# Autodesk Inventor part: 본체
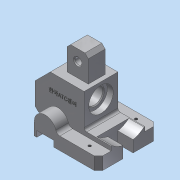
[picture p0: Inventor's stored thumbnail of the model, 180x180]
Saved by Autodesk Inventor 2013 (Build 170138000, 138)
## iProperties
Created: 2016-11
Part Number: 본체
Material: 알루미늄 6061
Document SubType Name: Modeling
Designer: Administrator
Density: 2.71 g/cm^3
Mass: 453.586 g
Surface Area: 313.387 cm^2
Volume: 167.375 cm^3
Author: Administrator
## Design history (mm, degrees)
sketch "스케치1"
  geometry: L1 (-38, 35)-(38, 35); L2 (38, 35)-(38, -35); L3 (38, -35)-(-38, -35); L4 (-38, -35)-(-38, 35); 3 further points
  constraints: 8 end point, 2 midpoint, 2 parallel, 1 horizontal, 1 horizontal alignment, 1 perpendicular, 1 vertical alignment
  dimensions: "d0" = 76 distance of L1.start L1.end; "d2" = 70 distance of L1.end L2.end
extrude "돌출1" new body sketch "스케치1" distance "d3" = 15; taper "d4" = 0 deg
sketch "스케치2"
  geometry: L1 (-35, 35)-(-35, -35); L2 (-15, 35)-(-15, -35); L3 (38, 35)-(-38, 35) reference; L4 (-38, -35)-(38, -35) reference; 1 further point
  constraints: 4 end point, 4 point on line, 1 parallel, 1 vertical
  dimensions: "d5" = 20 distance between parallel lines of L2 L1; "d6" = 3 distance from line of L1 L4.start
extrude "돌출2" cut sketch "스케치2" distance "d7" = 7; taper "d8" = 0 deg
sketch "스케치3"
  geometry: L1 (0, 0)-(76, 0) reference; A1 r 13 centre (13, 0) between (26, 0) and (0, 0); 1 further point
  constraints: 2 point on circle, 2 point on line, 1 centre point, 1 end point
  dimensions: "d9" = 26 diameter of A1
extrude "돌출3" join sketch "스케치3" distance "d11" = 70; taper "d12" = 0 deg
node "작업 평면1"
sketch "스케치4"
  geometry: L1 (-52, 20)-(6, 20); L2 (6, 20)-(6, -20); L3 (6, -20)-(-52, -20); L4 (-52, -20)-(-52, 20); L5 (38, -35)-(38, 35) reference; L6 (-38, 35)-(-38, -35) reference; 2 further points
  constraints: 8 end point, 2 parallel, 1 horizontal, 1 horizontal alignment, 1 midpoint, 1 perpendicular
  dimensions: "d117" = 40 distance between parallel lines of L3 L1; "d119" = 90 distance between parallel lines of L5 L4; "d120" = 58 distance from line of L1.start L2
extrude "돌출4" join sketch "스케치4" distance "d18" = 48; taper "d19" = 0 deg
chamfer "모따기1" distance "d20" = 18; stored, may be unused: second distance "d21" = 2, angle "d22" = 45 deg
chamfer "모따기2" distance "d23" = 4; stored, may be unused: second distance "d24" = 2, angle "d25" = 45 deg
chamfer "모따기3" distance "d26" = 5; stored, may be unused: second distance "d27" = 2, angle "d28" = 45 deg
chamfer "모따기4" distance "d29" = 5; stored, may be unused: second distance "d30" = 2, angle "d31" = 45 deg
fillet "모깎기1" dims "d32" = 5
node "작업 평면2"
sketch "스케치5"
  geometry: L1 (-24, 10)-(1, 10); L2 (1, 10)-(1, -10); L3 (1, -10)-(-24, -10); L4 (-24, -10)-(-24, 10); L5 (6, 20)-(6, -20) reference; 2 further points
  constraints: 8 end point, 2 parallel, 1 horizontal, 1 horizontal alignment, 1 midpoint, 1 perpendicular
  dimensions: "d34" = 5 distance between parallel lines of L2 L5; "d35" = 25 distance of L1.start L1.end; "d36" = 20 distance of L1.end L2.end
extrude "돌출5" join sketch "스케치5" distance "d37" = 40; taper "d38" = 0 deg
chamfer "모따기5" distance "d39" = 4; stored, may be unused: second distance "d40" = 2, angle "d41" = 45 deg
node "작업 평면3"
node "작업 평면5"
  node "작업 평면4"
sketch "스케치8"
  geometry: L1 (6, 20)-(6, -20) reference; L2 (6, 20)-(38, 20); L3 (38, 20)-(38, -20); L4 (38, -20)-(6, -20); L5 (6, -20)-(6, 20); L6 (-34, 20)-(6, 20) reference; L7 (6, -20)-(-34, -20) reference; 4 further points; 1 other entity
  constraints: 8 end point, 2 collinear, 2 parallel, 1 horizontal, 1 perpendicular, 1 point on line, 1 vertical, 1 other
extrude "돌출7" join sketch "스케치8" distance "d49" = 5; taper "d50" = 0 deg
sketch "스케치9"
  geometry: L1 (-5, 36)-(15, 36); L2 (15, 36)-(15, 24); L3 (15, 24)-(-5, 24); L4 (-5, 24)-(-5, 36); L5 (15, 60)-(15, 0) reference; L6 (0, 60)-(15, 60) reference; L7 (0, 50)-(0, 60) reference; L8 (0, 50)-(-5, 50) reference; L9 (-5, 10)-(-5, 50) reference; L10 (0, 10)-(-5, 10) reference; L11 (0, 0)-(0, 10) reference; L12 (15, 0)-(0, 0) reference; L13 (15, 60)-(15, 0) reference; 4 further points
  constraints: 8 end point, 5 midpoint, 2 parallel, 1 horizontal, 1 horizontal alignment, 1 perpendicular
  dimensions: "d51" = 12 distance of L1.end L2.end
extrude "돌출8" cut sketch "스케치9" distance "d53" = 18; taper "d54" = 0 deg
node "작업 평면6"
node "작업 평면7"
node "작업 평면8"
node "작업 평면9"
sketch "스케치14"
  geometry: L1 (-5, -38.894)-(-5, -1.106); L2 (-5, -14)-(-5, 0) reference; L3 (-5, -26)-(-5, -14) reference; L4 (-5, -40)-(-5, -26) reference; C1 r 10 at (-27, -20) reference; A1 r 29 centre (-27, -20) between (-5, -38.894) and (-5, -1.106); 1 further point
  constraints: 2 end point, 2 point on circle, 2 point on line, 1 centre point, 1 coincident, 1 collinear, 1 vertical
  dimensions: "d68" = 58 diameter of A1
extrude "돌출9" cut sketch "스케치14" distance "d70" = 18; taper "d71" = 0 deg
sketch "스케치15"
  geometry: L1 (-51, -20)-(-51, 20) reference; L2 (-51, 20)-(-38, 20) reference; L3 (-38, 20)-(-38, 35) reference; L4 (-38, 35)-(-7.708, 35) reference; L5 (-7.708, 20)-(-7.708, 35) reference; L6 (-7.708, 20)-(38, 20) reference; L7 (38, 20)-(38, 10.583) reference; L8 (38, 10.583)-(20, 10.583) reference; L9 (20, 10.583)-(20, -10.583) reference; L10 (20, -10.583)-(38, -10.583) reference; L11 (38, -10.583)-(38, -20) reference; L12 (38, -20)-(38, -30) reference; L13 (38, -30)-(33, -35) reference; L14 (33, -35)-(-7.708, -35) reference; L15 (-7.708, -35)-(-38, -35) reference; L16 (-38, -35)-(-38, -20) reference; L17 (-38, -20)-(-51, -20) reference; L18 (-7.708, 35)-(33, 35) reference; L19 (33, 35)-(38, 30) reference; L20 (38, 30)-(38, 20) reference; L21 (38, -20)-(-7.708, -20) reference; L22 (-7.708, -35)-(-7.708, -20) reference; L23 (6, 20)-(6, -20) reference; 3 further points
  constraints: 1 vertical alignment
  dimensions: "d72" = 55 distance of point (20, -27.5) point (20, 27.5); "d74" = 27.5 vertical distance of point (0, 0) point (20, 27.5); "d76" = 18 distance from line of point (20, 27.5) L20
hole "구멍2" sketch "스케치15" at (20, 27.5), (20, -27.5) diameter "d77" = 3.242; stored, may be unused: countersink angle "d81" = 90 deg, drill point angle "d83" = 0 deg; dims "d78" = 28, "d79" = 29, "d80" = 7, "d82" = 30
fillet "모깎기2" dims "d84" = 3
sketch "스케치16"
  geometry: L1 (0, 26)-(0, 0) reference; L2 (-11, -53)-(-11, -60) reference; L3 (-11, -60)-(-14, -60) reference; L4 (-14, -60)-(-14, -48) reference; L5 (-14, -48)-(-24, -48) reference; L6 (-24, -48)-(-28, -44) reference; L7 (-28, -44)-(-28, -18) reference; L8 (-28, -18)-(-10, 0) reference; L9 (-10, 0)-(0, 0) reference; L10 (0, 0)-(0, 26) reference; L11 (0, 26)-(4, 30) reference; L12 (4, 30)-(21, 30) reference; L13 (21, 30)-(25, 26) reference; L14 (25, 26)-(25, 0) reference; L15 (25, 0)-(30, 0) reference; L16 (30, 0)-(30, -37) reference; L17 (9, -53)-(-11, -53) reference; L18 (9, -60)-(9, -53) reference; L19 (62, -60)-(9, -60) reference; L20 (62, -45.221)-(62, -60) reference; L21 (44, -45.221)-(62, -45.221) reference; L22 (44, -40)-(44, -45.221) reference; L23 (33, -40)-(44, -40) reference; L24 (0, 0)-(25, 0) reference; L25 (62, -45)-(16.292, -45) reference; L26 (62, -45)-(62, -40) reference; L27 (33, -40)-(62, -40) reference; L28 (30, 0)-(30, -37) reference; L29 (30, 0)-(-10, 0) reference; L30 (-28, -18)-(-10, 0) reference; L31 (-28, -18)-(-28, -44) reference; L32 (-24, -48)-(-28, -44) reference; L33 (-14, -48)-(-24, -48) reference; L34 (-14, -45)-(-14, -48) reference; L35 (22, -32.5)-(22, -3.5) reference; L36 (22, -32.5)-(22, -3.5) reference; L37 (30, -3.5)-(30, -32.5) reference; A1 r 3 centre (33, -37) between (30, -37) and (33, -40) reference; A2 r 5 centre (16.292, -40) between (11.488, -41.389) and (16.292, -45) reference; A3 r 3 centre (33, -37) between (30, -37) and (33, -40) reference; A4 r 13 centre (-1, -45) between (11.488, -41.389) and (-14, -45) reference; 3 further points
  dimensions: "d88" = 12.5 distance from line of point (12.5, 17) L1; "d89" = 35 vertical distance of point (21, -18) point (12.5, 17)
hole "구멍3" sketch "스케치16" at (12.5, 17) diameter "d90" = 8; stored, may be unused: countersink angle "d94" = 90 deg, drill point angle "d96" = 0 deg; dims "d91" = 28, "d92" = 29, "d93" = 7, "d95" = 30
chamfer "모따기7" distance "d97" = 1; stored, may be unused: second distance "d98" = 2, angle "d99" = 45 deg
sketch "스케치17"
  geometry: L1 (44, 48)-(4, 48) reference; L2 (44, 48)-(44, 11) reference; 3 further points
  constraints: 1 coincident, 1 other
  dimensions: "d100" = 18 distance from line of point (19, 30) L1; "d101" = 25 distance from line of point (19, 30) L2
feature "엠보싱1" sketch "스케치17" dims "d0" = 76, "d2" = 70, "d102" = 0.5, "d103" = 0
sketch "스케치18"
  geometry: L1 (60, 50)-(60, 26) reference; L2 (37, 40)-(37, 0) reference; L3 (0, 40)-(37, 40) reference; L4 (0, 40)-(0, 0) reference; L5 (0, 0)-(37, 0) reference; 3 further points
  constraints: 1 horizontal alignment, 1 midpoint
  dimensions: "d104" = 42 distance from line of point (18, 20) L1
hole "구멍4" sketch "스케치18" at (18, 20) diameter "d105" = 20; stored, may be unused: countersink angle "d109" = 90 deg, drill point angle "d111" = 0 deg; dims "d106" = 6, "d107" = 29, "d108" = 7, "d110" = 8
chamfer "모따기8" distance "d112" = 1; stored, may be unused: second distance "d113" = 2, angle "d114" = 45 deg
node "솔리드1"
node "투영된 루프2"
node "투영된 루프3"
node "투영된 루프5"
node "절단 모서리 투영1"
node "절단 모서리 투영2"
other parameters: "d44" = 37, "d57" = -18, "d59" = 5
